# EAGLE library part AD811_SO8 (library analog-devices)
ANALOG DEVICES
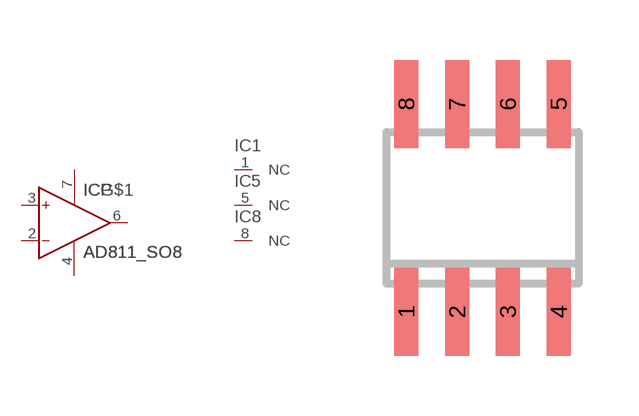
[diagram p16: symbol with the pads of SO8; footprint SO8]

Designator prefix IC; gates G$1=OP P=PWR+- 1=NC 5=NC 8=NC

## AD811_SO8 (MF: ALTERA CORPORATION; MPN: AD811JRZ; OC_FARNELL: unknown; OC_NEWARK: 82H2980)  [SO8]
1  1:NC  nc
2  G$1:IN-  in
3  G$1:IN+  in
4  P:V-  pwr
5  5:NC  nc
6  G$1:OUT  out
7  P:V+  pwr
8  8:NC  nc

## Footprint SO8 (pad centres in mm)
8-Lead Small Outline IC (SO-8) Source: http://www.analog.com/UploadedFiles/Data_Sheets/703465986AD8611_2_0.pdf
smd 0.6 x 2.2: 1 -1.905,-2.6; 2 -0.635,-2.6; 3 0.635,-2.6; 4 1.905,-2.6; 5 1.905,2.6; 6 0.635,2.6; 7 -0.635,2.6; 8 -1.905,2.6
